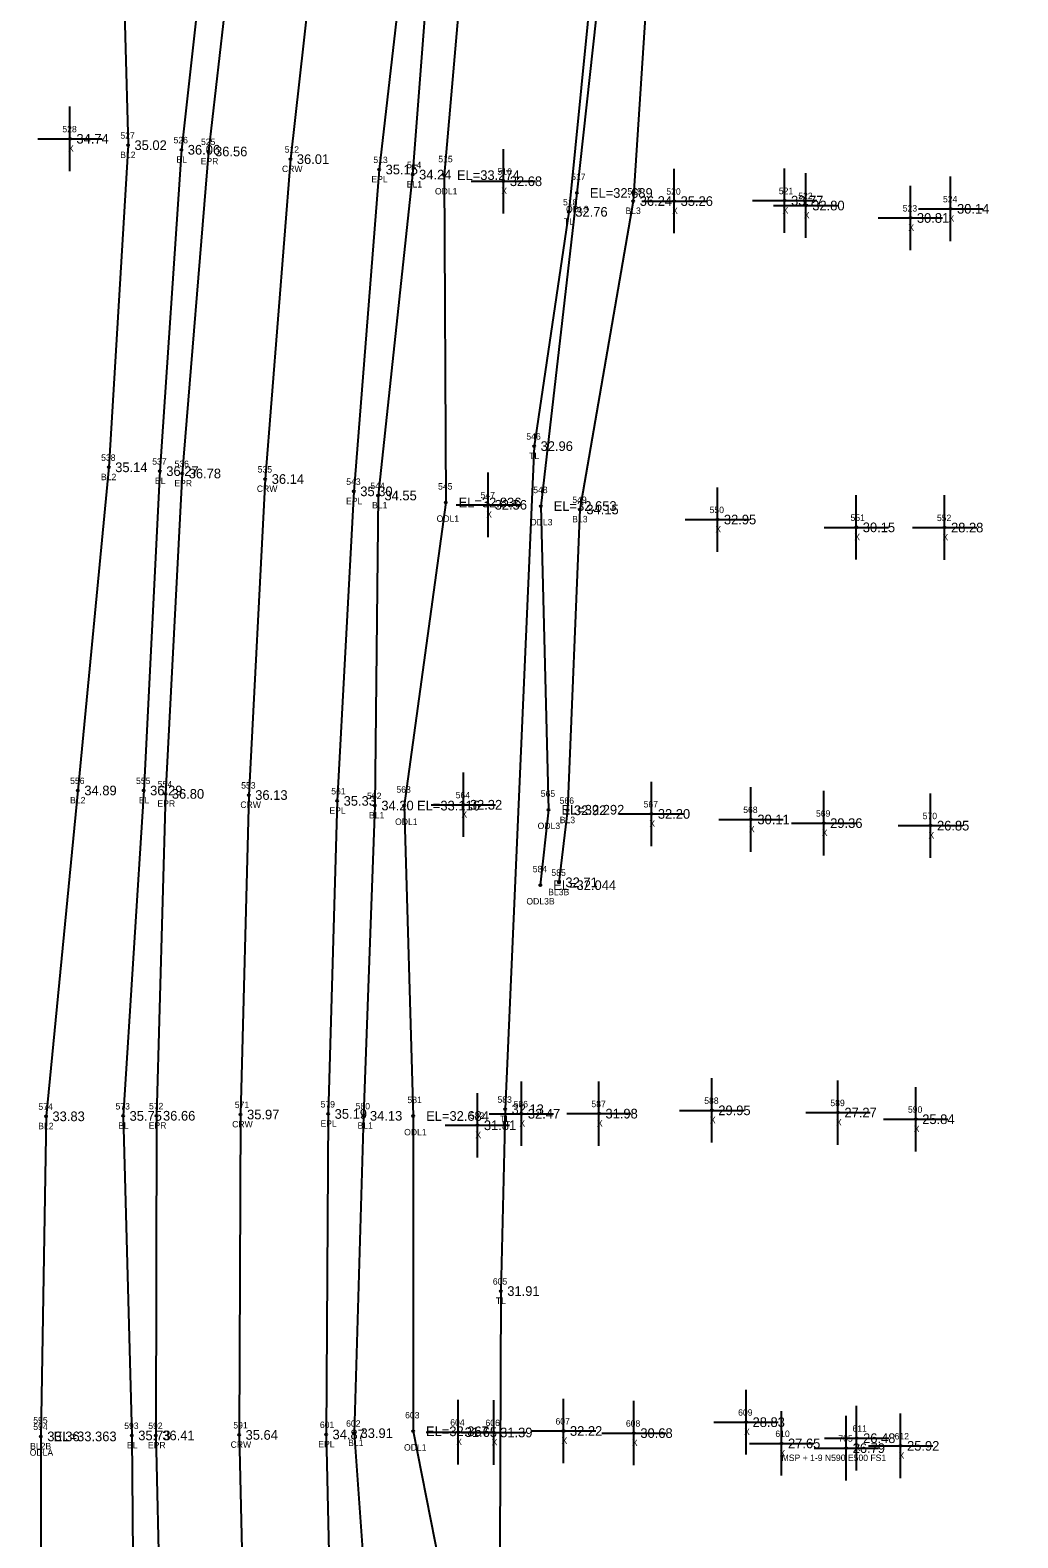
# Model space of a CAD drawing. Extents: x 2042211 to 2045853, y 303080 to 309569.
# Drawn here: x 2042807.4 to 2042960.7, y 307313.4 to 307547.4 of the extents above; entities that cross this region are included whole.
import ezdxf

# ---------------------------------------------------------------- set-up
doc = ezdxf.new("R2010")
doc.units = 0
for name, color, linetype in [('BR_500YR_SCOUR', 7, 'Continuous'), ('RD_DTM_BkLn1', 7, 'Continuous'), ('RD_DTM_BkLn_txCode', 7, 'Continuous'), ('RD_EX_H2O', 7, 'Continuous'), ('RD_EX_H2O_txCode', 7, 'Continuous'), ('RD_EX_Misc', 7, 'Continuous'), ('RD_EX_Misc_txCode', 7, 'Continuous'), ('RD_EX_Road', 7, 'Continuous'), ('RD_EX_Road_txCode', 7, 'Continuous'), ('RD_EX_TX_H2O_ELEV', 7, 'Continuous'), ('RD_EX_TX_Misc_ELEV', 7, 'Continuous'), ('RD_EX_TX_Road_ELEV', 7, 'Continuous'), ('RD_EX_TX_VEG_ELEV', 7, 'Continuous'), ('RD_EX_VEG_txCode', 7, 'Continuous'), ('RD_HC_Survey_ELEV', 7, 'Continuous'), ('RD_HC_Survey_txCode', 7, 'Continuous'), ('RD_SMD_Locator', 7, 'Continuous')]:
    doc.layers.add(name, color=color, linetype=linetype)

msp = doc.modelspace()

# ---------------------------------------------------------------- linework, layer by layer
at = {"layer": 'BR_500YR_SCOUR'}
msp.add_lwpolyline([(2043048.7, 308112.2), (2043032.62, 308087.68), (2043027.55, 308080.82), (2043013.5, 308043.09), (2042994.71, 307997.39), (2042983.47, 307967.75), (2042952.97, 307870.73), (2042935.66, 307809.47), (2042918.92, 307737.74), (2042902.79, 307636.4), (2042902.54, 307635.29), (2042891, 307519.21), (2042885.61, 307482.85), (2042881.1, 307379.92), (2042880.44, 307351.7), (2042880.19, 307284.9)], dxfattribs=at)
for centre in [(2042891, 307519.21), (2042885.61, 307482.85), (2042881.1, 307379.92), (2042880.44, 307351.7)]:
    msp.add_circle(centre, 0.15, dxfattribs=at)
at = {"layer": 'RD_DTM_BkLn1'}
for points in [[(2043161.13, 308408.97), (2043133.81, 308366.92), (2043082.92, 308281.6), (2043059.61, 308238.25), (2043036.96, 308193.55), (2043015.53, 308147.97), (2042995.29, 308102.87), (2042976.3, 308056.87), (2042958.8, 308010.83), (2042942.32, 307963.75), (2042927.06, 307916.53), (2042912.57, 307868.35), (2042899.47, 307820.61), (2042887.68, 307772.41), (2042877.12, 307722.98), (2042868.22, 307675.1), (2042860.12, 307626.05), (2042853.34, 307576.87), (2042847.77, 307527.39), (2042843.87, 307477.74), (2042841.31, 307428.69), (2042840.04, 307379.1), (2042839.81, 307329.37), (2042840.93, 307280.46)], [(2042869.74, 307776.07), (2042859.54, 307726.73), (2042851.31, 307678.22), (2042843.92, 307628.21), (2042836.41, 307578.73), (2042830.84, 307528.85), (2042827.5, 307478.96), (2042824.99, 307429.39), (2042821.8, 307378.88), (2042823.15, 307329.29), (2042823.59, 307279.35)], [(2042857.58, 307758.68), (2042851.06, 307728.52), (2042839.84, 307680.16), (2042833.97, 307629.9), (2042821.17, 307580.23), (2042822.56, 307529.56), (2042819.57, 307479.56), (2042814.78, 307429.4), (2042809.83, 307378.82), (2042809.03, 307329.14)], [(2042912.89, 307651.57), (2042909.19, 307620.12), (2042904.3, 307571.69), (2042901, 307520.89), (2042892.72, 307473.02), (2042890.79, 307426.32), (2042889.47, 307415.14)], [(2042873, 307595.28), (2042870.54, 307574.76), (2042866.75, 307524.99), (2042861.37, 307475.18), (2042860.89, 307427.06), (2042859.12, 307378.9), (2042857.66, 307329.64), (2042861.09, 307281.84)]]:
    msp.add_lwpolyline(points, dxfattribs=at)
at = {"layer": 'RD_EX_H2O'}
for points in [[(2042910.65, 307652.18), (2042905.42, 307621.57), (2042897.72, 307572.16), (2042892.26, 307522.14), (2042886.65, 307473.55), (2042887.85, 307426.41), (2042886.57, 307414.7)], [(2042877.76, 307594.41), (2042875.95, 307574.24), (2042871.62, 307524.91), (2042871.88, 307474.1), (2042865.43, 307427.05), (2042866.84, 307378.87), (2042866.82, 307329.93), (2042876.23, 307282.16)], [(2042809.03, 307329.14), (2042809.1, 307278.69), (2042813.16, 307229.38), (2042818.57, 307178.31), (2042821.22, 307157.54)]]:
    msp.add_lwpolyline(points, dxfattribs=at)
at = {"layer": 'RD_EX_Misc'}
for p, q in [((2042813.55, 307525.55), (2042813.55, 307535.55)), ((2042808.55, 307530.55), (2042818.55, 307530.55)), ((2042880.83, 307518.96), (2042880.83, 307528.96)), ((2042907.35, 307515.88), (2042907.35, 307525.88)), ((2042924.5, 307515.95), (2042924.5, 307525.95)), ((2042927.79, 307515.19), (2042927.79, 307525.19)), ((2042875.83, 307523.96), (2042885.83, 307523.96)), ((2042944.03, 307513.26), (2042944.03, 307523.26)), ((2042950.26, 307514.68), (2042950.26, 307524.68)), ((2042902.35, 307520.88), (2042912.35, 307520.88)), ((2042919.5, 307520.95), (2042929.5, 307520.95)), ((2042922.79, 307520.19), (2042932.79, 307520.19)), ((2042939.03, 307518.26), (2042949.03, 307518.26)), ((2042945.26, 307519.68), (2042955.26, 307519.68)), ((2042878.48, 307468.74), (2042878.48, 307478.74)), ((2042914.07, 307466.45), (2042914.07, 307476.45)), ((2042873.48, 307473.74), (2042883.48, 307473.74)), ((2042935.63, 307465.24), (2042935.63, 307475.24)), ((2042949.33, 307465.21), (2042949.33, 307475.21)), ((2042909.07, 307471.45), (2042919.07, 307471.45)), ((2042930.63, 307470.24), (2042940.63, 307470.24)), ((2042944.33, 307470.21), (2042954.33, 307470.21)), ((2042874.63, 307422.18), (2042874.63, 307432.18)), ((2042903.81, 307420.76), (2042903.81, 307430.76)), ((2042919.27, 307419.9), (2042919.27, 307429.9)), ((2042930.57, 307419.33), (2042930.57, 307429.33)), ((2042869.63, 307427.18), (2042879.63, 307427.18)), ((2042947.15, 307418.94), (2042947.15, 307428.94)), ((2042898.81, 307425.76), (2042908.81, 307425.76)), ((2042914.27, 307424.9), (2042924.27, 307424.9)), ((2042925.57, 307424.33), (2042935.57, 307424.33)), ((2042942.15, 307423.94), (2042952.15, 307423.94)), ((2042913.2, 307374.75), (2042913.2, 307384.75)), ((2042876.81, 307372.43), (2042876.81, 307382.43)), ((2042883.63, 307374.22), (2042883.63, 307384.22)), ((2042895.68, 307374.24), (2042895.68, 307384.24)), ((2042932.78, 307374.4), (2042932.78, 307384.4)), ((2042944.86, 307373.37), (2042944.86, 307383.37)), ((2042878.63, 307379.22), (2042888.63, 307379.22)), ((2042890.68, 307379.24), (2042900.68, 307379.24)), ((2042908.2, 307379.75), (2042918.2, 307379.75)), ((2042927.78, 307379.4), (2042937.78, 307379.4)), ((2042939.86, 307378.37), (2042949.86, 307378.37)), ((2042871.81, 307377.43), (2042881.81, 307377.43)), ((2042918.52, 307326.35), (2042918.52, 307336.35)), ((2042873.83, 307324.8), (2042873.83, 307334.8)), ((2042879.33, 307324.75), (2042879.33, 307334.75)), ((2042890.17, 307324.98), (2042890.17, 307334.98)), ((2042901.1, 307324.65), (2042901.1, 307334.65)), ((2042935.68, 307323.86), (2042935.68, 307333.86)), ((2042913.52, 307331.35), (2042923.52, 307331.35)), ((2042924.02, 307323.05), (2042924.02, 307333.05)), ((2042934.06, 307322.32), (2042934.06, 307332.32)), ((2042942.5, 307322.67), (2042942.5, 307332.67)), ((2042868.83, 307329.8), (2042878.83, 307329.8)), ((2042874.33, 307329.75), (2042884.33, 307329.75)), ((2042885.17, 307329.98), (2042895.17, 307329.98)), ((2042896.1, 307329.65), (2042906.1, 307329.65)), ((2042930.68, 307328.86), (2042940.68, 307328.86)), ((2042919.02, 307328.05), (2042929.02, 307328.05)), ((2042929.06, 307327.32), (2042939.06, 307327.32)), ((2042937.5, 307327.67), (2042947.5, 307327.67))]:
    msp.add_line(p, q, dxfattribs=at)
at = {"layer": 'RD_EX_Road'}
for points in [[(2042912.69, 307817.39), (2042901.29, 307769.38), (2042891.09, 307720.95), (2042881.8, 307672.88), (2042874.23, 307624.44), (2042867.25, 307575.38), (2042861.55, 307525.78), (2042857.62, 307475.83), (2042855.03, 307427.78), (2042853.64, 307379.19), (2042853.31, 307329.44), (2042854.43, 307281.38)], [(2042875.38, 307775.02), (2042864.88, 307726.03), (2042855.57, 307677.22), (2042847.6, 307627.85), (2042840.73, 307578.32), (2042835.07, 307528.58), (2042830.98, 307478.6), (2042828.36, 307428.87), (2042826.99, 307378.91), (2042826.88, 307329.29), (2042828.01, 307279.82)]]:
    msp.add_lwpolyline(points, dxfattribs=at)
at = {"layer": 'RD_SMD_Locator'}
for centre in [(2042813.55, 307530.55), (2042822.56, 307529.56), (2042830.84, 307528.85), (2042835.07, 307528.58), (2042847.77, 307527.39), (2042861.55, 307525.78), (2042866.75, 307524.99), (2042871.62, 307524.91), (2042880.83, 307523.96), (2042892.26, 307522.14), (2042901, 307520.89), (2042907.35, 307520.88), (2042924.5, 307520.95), (2042927.79, 307520.19), (2042944.03, 307518.26), (2042950.26, 307519.68), (2042819.57, 307479.56), (2042827.5, 307478.96), (2042830.98, 307478.6), (2042843.87, 307477.74), (2042857.62, 307475.83), (2042861.37, 307475.18), (2042871.88, 307474.1), (2042878.48, 307473.74), (2042886.65, 307473.55), (2042892.72, 307473.02), (2042914.07, 307471.45), (2042935.63, 307470.24), (2042949.33, 307470.21), (2042814.78, 307429.4), (2042824.99, 307429.39), (2042828.36, 307428.87), (2042841.31, 307428.69), (2042855.03, 307427.78), (2042860.89, 307427.06), (2042865.43, 307427.05), (2042874.63, 307427.18), (2042887.85, 307426.41), (2042890.79, 307426.32), (2042903.81, 307425.76), (2042919.27, 307424.9), (2042930.57, 307424.33), (2042947.15, 307423.94), (2042889.47, 307415.14), (2042886.57, 307414.7), (2042809.83, 307378.82), (2042821.8, 307378.88), (2042826.99, 307378.91), (2042840.04, 307379.1), (2042853.64, 307379.19), (2042859.12, 307378.9), (2042866.84, 307378.87), (2042883.63, 307379.22), (2042895.68, 307379.24), (2042913.2, 307379.75), (2042932.78, 307379.4), (2042944.86, 307378.37), (2042876.81, 307377.43), (2042918.52, 307331.35), (2042809.03, 307329.14), (2042809.03, 307329.14), (2042823.15, 307329.29), (2042826.88, 307329.29), (2042839.81, 307329.37), (2042853.31, 307329.44), (2042857.66, 307329.64), (2042866.82, 307329.93), (2042873.83, 307329.8), (2042879.33, 307329.75), (2042890.17, 307329.98), (2042901.1, 307329.65), (2042935.68, 307328.86), (2042924.02, 307328.05), (2042934.06, 307327.32), (2042942.5, 307327.67)]:
    msp.add_circle(centre, 0.15, dxfattribs=at)

# ---------------------------------------------------------------- texts
at = {"layer": 'RD_DTM_BkLn_txCode'}
for s, p in [('527', (2042821.38, 307530.56)), ('526', (2042829.63, 307529.85)), ('BL2', (2042821.35, 307527.56)), ('BL', (2042830.08, 307526.85)), ('514', (2042865.86, 307525.99)), ('BL1', (2042865.83, 307522.99)), ('519', (2042900.1, 307521.89)), ('BL3', (2042899.79, 307518.89)), ('538', (2042818.39, 307480.56)), ('537', (2042826.32, 307479.96)), ('BL2', (2042818.36, 307477.56)), ('BL', (2042826.74, 307476.96)), ('544', (2042860.19, 307476.18)), ('BL1', (2042860.45, 307473.18)), ('549', (2042891.54, 307474.02)), ('BL3', (2042891.52, 307471.02)), ('556', (2042813.57, 307430.4)), ('555', (2042823.81, 307430.39)), ('BL2', (2042813.57, 307427.4)), ('BL', (2042824.24, 307427.39)), ('562', (2042859.68, 307428.06)), ('566', (2042889.57, 307427.32)), ('BL1', (2042859.97, 307425.06)), ('BL3', (2042889.59, 307424.32)), ('585', (2042888.29, 307416.14)), ('BL3B', (2042887.79, 307413.14)), ('574', (2042808.65, 307379.82)), ('573', (2042820.62, 307379.88)), ('580', (2042857.9, 307379.9)), ('BL2', (2042808.62, 307376.82)), ('BL', (2042821.04, 307376.88)), ('BL1', (2042858.2, 307376.9)), ('594', (2042807.85, 307330.14)), ('593', (2042821.97, 307330.29)), ('602', (2042856.42, 307330.64)), ('BL1', (2042856.74, 307327.64)), ('BL2B', (2042807.36, 307327.14)), ('BL', (2042822.4, 307327.29))]:
    msp.add_text(s, height=1, dxfattribs=at).set_placement(p)
at = {"layer": 'RD_EX_H2O_txCode'}
for s, p in [('515', (2042870.73, 307526.91)), ('517', (2042891.36, 307524.14)), ('ODL1', (2042870.21, 307521.91)), ('ODL3', (2042890.56, 307519.14)), ('545', (2042870.7, 307476.1)), ('548', (2042885.47, 307475.55)), ('ODL1', (2042870.47, 307471.1)), ('ODL3', (2042884.96, 307470.55)), ('563', (2042864.23, 307429.05)), ('565', (2042886.64, 307428.41)), ('ODL1', (2042864.02, 307424.05)), ('ODL3', (2042886.15, 307423.41)), ('584', (2042885.39, 307416.7)), ('ODL3B', (2042884.41, 307411.7)), ('581', (2042865.94, 307380.87)), ('ODL1', (2042865.43, 307375.87)), ('595', (2042807.85, 307331.14)), ('603', (2042865.58, 307331.93)), ('ODLA', (2042807.3, 307326.14)), ('ODL1', (2042865.41, 307326.93))]:
    msp.add_text(s, height=1, dxfattribs=at).set_placement(p)
at = {"layer": 'RD_EX_Misc_txCode'}
for s, p in [('528', (2042812.37, 307531.55)), ('X', (2042813.24, 307528.55)), ('516', (2042879.91, 307524.96)), ('X', (2042880.52, 307521.96)), ('520', (2042906.13, 307521.88)), ('521', (2042923.6, 307521.95)), ('522', (2042926.61, 307521.19)), ('524', (2042949.08, 307520.68)), ('X', (2042907.03, 307518.88)), ('X', (2042924.18, 307518.95)), ('X', (2042927.48, 307518.19)), ('523', (2042942.84, 307519.26)), ('X', (2042949.95, 307517.68)), ('X', (2042943.71, 307516.26)), ('547', (2042877.3, 307474.74)), ('X', (2042878.17, 307471.74)), ('550', (2042912.85, 307472.45)), ('551', (2042934.73, 307471.24)), ('552', (2042948.14, 307471.21)), ('X', (2042913.75, 307469.45)), ('X', (2042935.31, 307468.24)), ('X', (2042949.01, 307468.21)), ('564', (2042873.43, 307428.18)), ('567', (2042902.61, 307426.76)), ('568', (2042918.07, 307425.9)), ('X', (2042874.32, 307425.18)), ('X', (2042903.5, 307423.76)), ('569', (2042929.37, 307425.33)), ('570', (2042945.93, 307424.94)), ('X', (2042918.96, 307422.9)), ('X', (2042930.26, 307422.33)), ('X', (2042946.83, 307421.94)), ('586', (2042882.43, 307380.22)), ('587', (2042894.5, 307380.24)), ('588', (2042912.02, 307380.75)), ('589', (2042931.6, 307380.4)), ('590', (2042943.64, 307379.37)), ('582', (2042875.63, 307378.43)), ('X', (2042883.32, 307377.22)), ('X', (2042895.36, 307377.24)), ('X', (2042912.89, 307377.75)), ('X', (2042932.47, 307377.4)), ('X', (2042876.49, 307375.43)), ('X', (2042944.55, 307376.37)), ('609', (2042917.28, 307332.35)), ('604', (2042872.59, 307330.8)), ('606', (2042878.06, 307330.75)), ('607', (2042888.93, 307330.98)), ('608', (2042899.86, 307330.65)), ('611', (2042935.04, 307329.86)), ('X', (2042873.52, 307327.8)), ('X', (2042879.01, 307327.75)), ('X', (2042889.86, 307327.98)), ('X', (2042900.79, 307327.65)), ('X', (2042918.21, 307329.35)), ('610', (2042923.06, 307329.05)), ('705', (2042932.84, 307328.32)), ('612', (2042941.58, 307328.67)), ('X', (2042923.71, 307326.05)), ('MSP + 1-9 N590 E500 FS1', (2042924.03, 307325.32)), ('X', (2042935.37, 307326.86)), ('X', (2042942.19, 307325.67))]:
    msp.add_text(s, height=1, dxfattribs=at).set_placement(p)
at = {"layer": 'RD_EX_Road_txCode'}
for s, p in [('525', (2042833.89, 307529.58)), ('EPR', (2042833.84, 307526.58)), ('513', (2042860.65, 307526.78)), ('EPL', (2042860.35, 307523.78)), ('536', (2042829.78, 307479.6)), ('EPR', (2042829.75, 307476.6)), ('543', (2042856.44, 307476.83)), ('EPL', (2042856.42, 307473.83)), ('554', (2042827.18, 307429.87)), ('561', (2042854.11, 307428.78)), ('EPR', (2042827.13, 307426.87)), ('EPL', (2042853.83, 307425.78)), ('572', (2042825.81, 307379.91)), ('579', (2042852.46, 307380.19)), ('EPR', (2042825.77, 307376.91)), ('EPL', (2042852.44, 307377.19)), ('592', (2042825.7, 307330.29)), ('601', (2042852.35, 307330.44)), ('EPR', (2042825.65, 307327.29)), ('EPL', (2042852.1, 307327.44))]:
    msp.add_text(s, height=1, dxfattribs=at).set_placement(p)
at = {"layer": 'RD_EX_TX_H2O_ELEV'}
for s, p in [('EL=33.274', (2042873.62, 307524.16)), ('EL=32.689', (2042894.26, 307521.39)), ('EL=32.836', (2042873.88, 307473.35)), ('EL=32.653', (2042888.65, 307472.8)), ('EL=33.116', (2042867.43, 307426.3)), ('EL=32.292', (2042889.85, 307425.66)), ('EL=32.044', (2042888.57, 307413.95)), ('EL=32.634', (2042868.84, 307378.12)), ('EL=33.363', (2042811.03, 307328.39)), ('EL=32.367', (2042868.82, 307329.18))]:
    msp.add_text(s, height=1.5, dxfattribs=at).set_placement(p)
at = {"layer": 'RD_EX_TX_Misc_ELEV'}
for s, p in [('34.74', (2042814.55, 307529.8)), ('35.02', (2042823.56, 307528.81)), ('36.06', (2042831.84, 307528.1)), ('34.24', (2042867.75, 307524.24)), ('32.68', (2042881.83, 307523.21)), ('36.24', (2042902, 307520.14)), ('35.26', (2042908.35, 307520.13)), ('33.77', (2042925.5, 307520.2)), ('32.80', (2042928.79, 307519.44)), ('30.14', (2042951.26, 307518.93)), ('30.81', (2042945.03, 307517.51)), ('35.14', (2042820.57, 307478.81)), ('36.27', (2042828.5, 307478.21)), ('34.55', (2042862.37, 307474.43)), ('32.56', (2042879.48, 307472.99)), ('34.15', (2042893.72, 307472.27)), ('32.95', (2042915.07, 307470.7)), ('30.15', (2042936.63, 307469.49)), ('28.28', (2042950.33, 307469.46)), ('34.89', (2042815.78, 307428.65)), ('36.29', (2042825.99, 307428.64)), ('34.20', (2042861.89, 307426.31)), ('32.32', (2042875.63, 307426.43)), ('32.92', (2042891.79, 307425.57)), ('32.20', (2042904.81, 307425.01)), ('30.11', (2042920.27, 307424.15)), ('29.36', (2042931.57, 307423.58)), ('26.85', (2042948.15, 307423.19)), ('32.71', (2042890.47, 307414.39)), ('32.47', (2042884.63, 307378.47)), ('31.98', (2042896.68, 307378.49)), ('29.95', (2042914.2, 307379)), ('27.27', (2042933.78, 307378.65)), ('33.83', (2042810.83, 307378.07)), ('35.75', (2042822.8, 307378.13)), ('34.13', (2042860.12, 307378.15)), ('31.81', (2042877.81, 307376.68)), ('25.84', (2042945.86, 307377.62)), ('28.83', (2042919.52, 307330.6)), ('33.36', (2042810.03, 307328.39)), ('35.73', (2042824.15, 307328.54)), ('33.91', (2042858.66, 307328.89)), ('31.65', (2042874.83, 307329.05)), ('31.39', (2042880.33, 307329)), ('32.22', (2042891.17, 307329.23)), ('30.68', (2042902.1, 307328.9)), ('27.65', (2042925.02, 307327.3)), ('26.48', (2042936.68, 307328.11)), ('26.79', (2042935.06, 307326.57)), ('25.92', (2042943.5, 307326.92))]:
    msp.add_text(s, height=1.5, dxfattribs=at).set_placement(p)
at = {"layer": 'RD_EX_TX_Road_ELEV'}
for s, p in [('36.56', (2042836.07, 307527.83)), ('35.15', (2042862.55, 307525.03)), ('36.78', (2042831.98, 307477.85)), ('35.30', (2042858.62, 307475.08)), ('36.80', (2042829.36, 307428.12)), ('35.33', (2042856.03, 307427.03)), ('35.19', (2042854.64, 307378.44)), ('36.66', (2042827.99, 307378.16)), ('36.41', (2042827.88, 307328.54)), ('34.87', (2042854.31, 307328.69))]:
    msp.add_text(s, height=1.5, dxfattribs=at).set_placement(p)
at = {"layer": 'RD_EX_TX_VEG_ELEV'}
for s, p in [('32.76', (2042892, 307518.46)), ('32.96', (2042886.61, 307482.1)), ('32.13', (2042882.1, 307379.17)), ('31.91', (2042881.44, 307350.95))]:
    msp.add_text(s, height=1.5, dxfattribs=at).set_placement(p)
at = {"layer": 'RD_EX_VEG_txCode'}
for s, p in [('518', (2042890.1, 307520.21)), ('TL', (2042890.23, 307517.21)), ('546', (2042884.4, 307483.85)), ('TL', (2042884.84, 307480.85)), ('583', (2042879.92, 307380.92)), ('TL', (2042880.33, 307377.92)), ('605', (2042879.2, 307352.7)), ('TL', (2042879.67, 307349.7))]:
    msp.add_text(s, height=1, dxfattribs=at).set_placement(p)
at = {"layer": 'RD_HC_Survey_ELEV'}
for s, p in [('36.01', (2042848.77, 307526.64)), ('36.14', (2042844.87, 307476.99)), ('36.13', (2042842.31, 307427.94)), ('35.97', (2042841.04, 307378.35)), ('35.64', (2042840.81, 307328.62))]:
    msp.add_text(s, height=1.5, dxfattribs=at).set_placement(p)
at = {"layer": 'RD_HC_Survey_txCode'}
for s, p in [('512', (2042846.88, 307528.39)), ('CRW', (2042846.46, 307525.39)), ('535', (2042842.69, 307478.74)), ('CRW', (2042842.56, 307475.74)), ('553', (2042840.13, 307429.69)), ('CRW', (2042840, 307426.69)), ('571', (2042839.14, 307380.1)), ('CRW', (2042838.73, 307377.1)), ('591', (2042838.91, 307330.37)), ('CRW', (2042838.49, 307327.37))]:
    msp.add_text(s, height=1, dxfattribs=at).set_placement(p)

doc.saveas('drawing.dxf')
